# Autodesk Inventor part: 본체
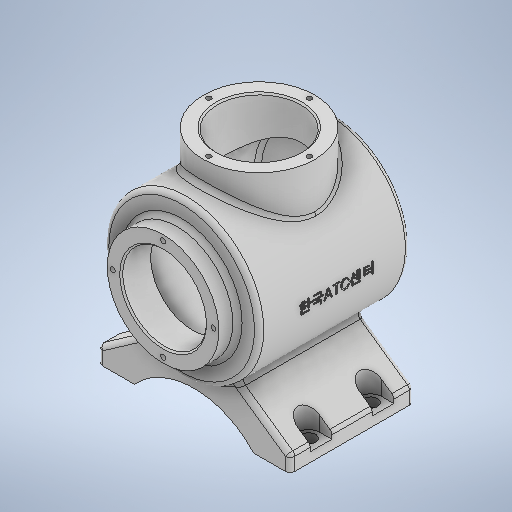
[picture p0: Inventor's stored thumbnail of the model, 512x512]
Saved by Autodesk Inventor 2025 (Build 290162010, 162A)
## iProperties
Created: 2024-07
Part Number: 본체
Material: 일반
Document SubType Name: Modeling
Designer: 학생
Density: 1 g/cm^3
Appearance: 기본값
Author: 학생
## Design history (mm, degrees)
sketch "스케치1"
  geometry: C1 r 50 at (0, 0); 1 further point
  constraints: 1 centre point, 1 coincident
  dimensions: "d0" = 100 diameter of C1
extrude "돌출1" new body sketch "스케치1" stored distance "d1" = 108; taper "d2" = 0 deg
sketch "스케치3"
  geometry: L1 (-50, -54)-(50, -54) reference; L2 (0, -54)-(50, -54); L3 (50, -54)-(50, -42.336); L4 (50, -54)-(50, 54) reference; L5 (0, -80.053)-(0, 82.175) reference; A1 r 113 centre (0, 59) between (0, -54) and (50, -42.336); 1 further point
  constraints: 4 end point, 2 point on circle, 1 centre point, 1 collinear, 1 midpoint, 1 point on line, 1 vertical alignment
  dimensions: "d5" = 226 diameter of A1
sketch "스케치4"
  geometry: C1 r 36 at (0, 0); 1 further point
  constraints: 1 centre point, 1 coincident
  dimensions: "d7" = 72 diameter of C1
extrude "돌출2" join sketch "스케치4" distance "d8" = 12; taper "d9" = 0 deg
sketch "스케치5"
  geometry: C1 r 27 at (0, 0); 1 further point
  constraints: 1 centre point, 1 coincident
  dimensions: "d10" = 54 diameter of C1
extrude "돌출3" cut sketch "스케치5" distance "d11" = 19; taper "d12" = 0 deg
sketch "스케치6"
  geometry: C1 r 43 at (0, 0); 1 further point
  constraints: 1 centre point, 1 coincident
  dimensions: "d13" = 86 diameter of C1
extrude "돌출4" cut sketch "스케치6" distance "d14" = 94; taper "d15" = 0 deg
sketch "스케치7"
  geometry: L1 (-43, -47)-(43, -47) reference; L2 (0, -47)-(-43, -47); L3 (-43, 47)-(-43, -47) reference; L4 (-43, -37.887)-(-43, -47); L5 (0, -78)-(0, 90) reference; A1 r 106 centre (0, 59) between (-43, -37.887) and (0, -47); 2 further points
  constraints: 4 end point, 2 point on circle, 1 centre point, 1 collinear, 1 midpoint, 1 perpendicular, 1 point on line, 1 vertical alignment
  dimensions: "d24" = 212 diameter of A1
revolve "회전2" sketch "스케치7" stored, may be unused: angle "d25" = 90 deg
revolve "회전3" stored, may be unused: angle "d26" = 90 deg
fillet "모깎기1" dims "d31" = 3
node "작업 평면1"
sketch "스케치8"
  geometry: L1 (-62, -77)-(-38.5, -77); L2 (-62, -77)-(-62, -67); L3 (-62, -67)-(-26.694, -42.278); L4 (38.5, -77)-(62, -77); L5 (62, -77)-(62, -67); L6 (62, -67)-(26.694, -42.278); A1 r 50 centre (0, 0) between (-26.694, -42.278) and (26.694, -42.278) reference; A2 r 52.096 centre (0, -112.096) between (38.5, -77) and (-38.5, -77); 2 further points
  constraints: 12 end point, 5 point on circle, 4 horizontal alignment, 3 equal length, 2 horizontal, 2 vertical, 1 centre point
  dimensions: "d33" = 17 distance from line of point (0, -60) L1; "d34" = 10 distance of L1.start L2.end; "d35" = 55 deg angle of L5 L6; "d36" = 77 distance from line of L4 point (0, 0); "d37" = 77 distance of L4.start L1.end; "d38" = 124 distance between parallel lines of L5 L2
extrude "돌출5" join sketch "스케치8" distance "d39" = 80; taper "d40" = 0 deg
fillet "모깎기2" dims "d41" = 3
fillet "모깎기3" dims "d42" = 3
chamfer "모따기1" distance "d43" = 1; stored, may be unused: second distance "d44" = 2, angle "d45" = 45 deg
node "작업 평면2"
sketch "스케치9"
  geometry: L1 (36, 66)-(-36, 66) reference; L2 (0, 66)-(0, 4); C1 r 36 at (0, 4); 1 further point
  constraints: 2 end point, 1 centre point, 1 coincident, 1 midpoint, 1 vertical
  dimensions: "d47" = 62 distance of L2.start L2.end; "d48" = 72 diameter of C1
extrude "돌출6" join sketch "스케치9" stored distance "d49" = 0; taper "d50" = 0 deg
sketch "스케치10" dims "d52" = 65
  geometry: C1 r 36 at (0, 0) reference; C2 r 27 at (0, 0); 6 further points
  constraints: 2 coincident, 2 vertical alignment, 1 centre point, 7 other
  dimensions: "d51" = 54 diameter of C2; "d55" = 360 deg dimension on C1.centre point (0, 32.5) (derived)
  node "스케치 - 원형 패턴1" dims "d55" = 360 deg (derived)
extrude "돌출7" cut sketch "스케치10" distance "d57" = 51.75; taper "d58" = 0 deg
hole "구멍1" sketch "스케치10" diameter "d59" = 3.242; stored, may be unused: countersink angle "d63" = 90 deg, drill point angle "d65" = 120 deg; dims "d60" = 8, "d61" = 4, "d62" = 2, "d64" = 10
chamfer "모따기2" distance "d66" = 1; stored, may be unused: second distance "d67" = 2, angle "d68" = 45 deg
fillet "모깎기4" dims "d69" = 3
fillet "모깎기5" dims "d70" = 3
sketch "스케치11" dims "d71" = 65
  geometry: 6 further points
  constraints: 2 vertical alignment, 1 coincident, 7 other
  dimensions: "d74" = 360 deg dimension on point (0, 0) point (0, 32.5) (derived)
hole "구멍2" sketch "스케치11" at (0, 32.5), (-32.5, 0), (0, -32.5), (32.5, 0) diameter "d76" = 3.242; stored, may be unused: countersink angle "d80" = 90 deg, drill point angle "d82" = 120 deg; dims "d77" = 8, "d78" = 4, "d79" = 2, "d81" = 10
node "작업 평면3"
sketch "스케치13"
  geometry: L1 (-97.5, 80)-(-65.074, 80) reference; L2 (-99.221, 77)-(-99.221, 3) reference; L3 (-100.5, 3)-(-100.5, 77) reference; 5 further points
  constraints: 2 horizontal alignment, 2 vertical alignment
  dimensions: "d89" = 108 distance of point (15.5, 60) point (-92.5, 60); "d92" = 40 distance of point (15.5, 20) point (15.5, 60); "d93" = 20 distance from line of point (-92.5, 60) L1; "d95" = 8 distance from line of L3 point (-92.5, 20)
hole "구멍4" sketch "스케치13" at (-92.5, 60), (-92.5, 20), (15.5, 60), (15.5, 20) diameter "d103" = 9; stored, may be unused: countersink angle "d107" = 90 deg, drill point angle "d109" = 0 deg; dims "d104" = 6, "d105" = 14, "d106" = 19, "d108" = 25
sketch "스케치14"
  geometry: L1 (15.5, 13)-(23.5, 13); L2 (15.5, 27)-(23.5, 27); L3 (23.5, 77)-(23.5, 3) reference; L4 (23.5, 13)-(23.5, 27); L5 (23.5, 40)-(-100.5, 40); L6 (-100.5, 3)-(-100.5, 77) reference; L7 (15.5, 67)-(23.5, 67); L8 (15.5, 53)-(23.5, 53); L9 (23.5, 53)-(23.5, 67); L10 (-38.5, 40)-(-38.5, 87.276); L11 (-92.5, 13)-(-100.5, 13); L12 (-92.5, 27)-(-100.5, 27); L13 (-92.5, 53)-(-100.5, 53); L14 (-92.5, 67)-(-100.5, 67); L15 (-100.5, 13)-(-100.5, 27); L16 (-100.5, 53)-(-100.5, 67); A1 r 7 centre (15.5, 20) between (22.221, 21.957) and (22.221, 18.043) reference; A2 r 7 centre (-92.5, 20) between (-99.221, 18.043) and (-99.221, 21.957) reference; A3 r 7 centre (-92.5, 60) between (-99.221, 58.043) and (-99.221, 61.957) reference; A4 r 7 centre (15.5, 60) between (22.221, 61.957) and (22.221, 58.043) reference; 1 further point
  constraints: 28 end point, 12 symmetric about line, 3 midpoint, 3 vertical, 2 horizontal, 2 point on circle, 2 point on line, 2 tangent, 1 collinear
extrude "돌출8" cut sketch "스케치14" distance "d110" = 19; taper "d111" = 0 deg
node "작업 평면4"
sketch "스케치16"
  geometry: L1 (36, 66)-(-36, 66) reference; L2 (0, 66)-(0, 4); 2 further points
  constraints: 2 end point, 1 coincident, 1 midpoint, 1 vertical, 1 other
  dimensions: "d113" = 62 distance of L2.start L2.end
feature "엠보싱1" sketch "스케치16" dims "d114" = 0.5, "d115" = 0
node "솔리드1"
node "스케치 - 원형 패턴2" dims "d74" = 360 deg (derived)
feature "A9D066F2-1C7D-4E18-AEED-F7BC21143FA4" dims "d103" = 9, "d104" = 6, "d105" = 14, "d106" = 19, "d107" = 90 deg, "d108" = 25, "d109" = 0
other parameters: "d27" = 0.5, "d28" = 2, "d29" = 0, "d46" = 65, "d87" = -25, "d112" = 59.5
